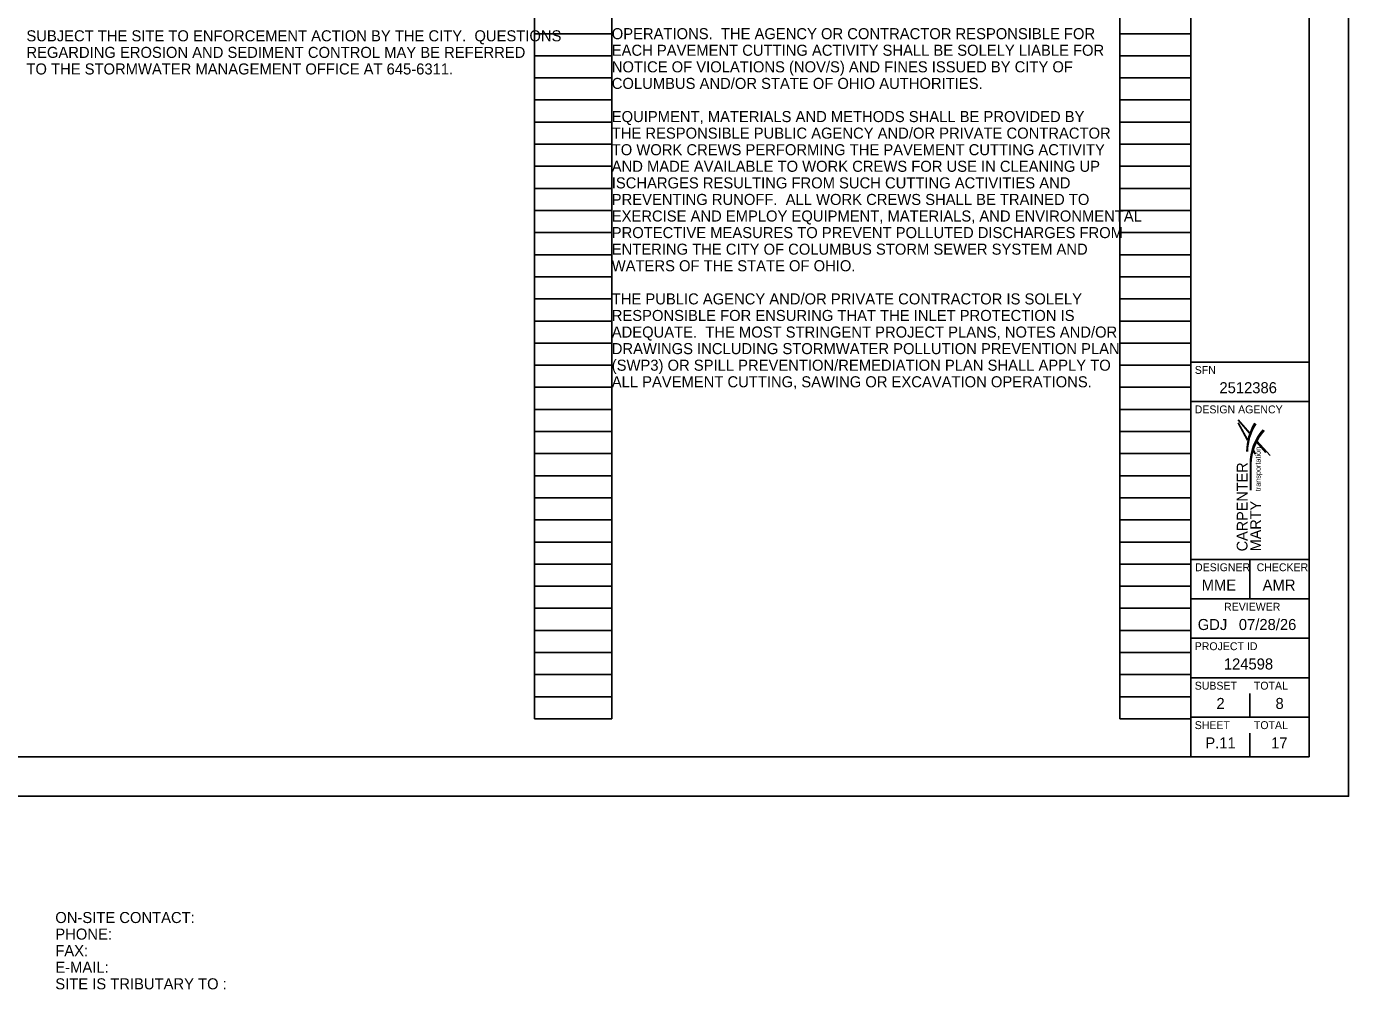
# Model space of a CAD drawing. Extents: x 0 to 34, y -2.4 to 26.3.
# Drawn here: x 17.24 to 34, y -2.45 to 9.75 of the extents above; entities that cross this region are included whole.
import ezdxf

# ---------------------------------------------------------------- set-up
doc = ezdxf.new("R2010")
doc.units = 0
for name, color, linetype in [('BR_P_Gen_Text', 7, 'Continuous'), ('SH_Border', 7, 'Continuous'), ('SH_Cut_Line', 7, 'Continuous'), ('SH_Data', 7, 'Continuous'), ('SH_Text', 7, 'Continuous')]:
    doc.layers.add(name, color=color, linetype=linetype)

msp = doc.modelspace()

# ---------------------------------------------------------------- linework, layer by layer
at = {"layer": 'SH_Border'}
for p, q in [((32, 0.5), (32, 21.5)), ((32, 5.5), (33.5, 5.5)), ((32, 5), (33.5, 5)), ((32, 3), (33.5, 3)), ((32.75, 3), (32.75, 2.5)), ((32, 2.5), (33.5, 2.5)), ((32, 2), (33.5, 2)), ((32, 1.5), (33.5, 1.5)), ((32, 1), (33.5, 1))]:
    msp.add_line(p, q, dxfattribs=at)
msp.add_lwpolyline([(1.5, 21.5), (33.5, 21.5), (33.5, 0.5), (1.5, 0.5)], close=True, dxfattribs=at)
at = {"layer": 'SH_Cut_Line'}
msp.add_lwpolyline([(0, 0), (34, 0), (34, 22), (0, 22)], close=True, dxfattribs=at)
at = {"layer": 'SH_Data'}
for p, q in [((23.68, 0.98), (23.68, 21.14)), ((24.66, 0.98), (24.66, 21.14)), ((31.1, 0.98), (31.1, 21.14)), ((32, 0.98), (32, 21.14)), ((23.68, 9.66), (24.66, 9.66)), ((31.1, 9.66), (32, 9.66)), ((23.68, 9.38), (24.66, 9.38)), ((31.1, 9.38), (32, 9.38)), ((23.68, 9.1), (24.66, 9.1)), ((31.1, 9.1), (32, 9.1)), ((23.68, 8.82), (24.66, 8.82)), ((31.1, 8.82), (32, 8.82)), ((23.68, 8.54), (24.66, 8.54)), ((31.1, 8.54), (32, 8.54)), ((23.68, 8.26), (24.66, 8.26)), ((31.1, 8.26), (32, 8.26)), ((23.68, 7.98), (24.66, 7.98)), ((31.1, 7.98), (32, 7.98)), ((23.68, 7.7), (24.66, 7.7)), ((31.1, 7.7), (32, 7.7)), ((23.68, 7.42), (24.66, 7.42)), ((31.1, 7.42), (32, 7.42)), ((23.68, 7.14), (24.66, 7.14)), ((31.1, 7.14), (32, 7.14)), ((23.68, 6.86), (24.66, 6.86)), ((31.1, 6.86), (32, 6.86)), ((23.68, 6.58), (24.66, 6.58)), ((31.1, 6.58), (32, 6.58)), ((23.68, 6.3), (24.66, 6.3)), ((31.1, 6.3), (32, 6.3)), ((23.68, 6.02), (24.66, 6.02)), ((31.1, 6.02), (32, 6.02)), ((23.68, 5.74), (24.66, 5.74)), ((31.1, 5.74), (32, 5.74)), ((23.68, 5.46), (24.66, 5.46)), ((31.1, 5.46), (32, 5.46)), ((23.68, 5.18), (24.66, 5.18)), ((31.1, 5.18), (32, 5.18)), ((23.68, 4.9), (24.66, 4.9)), ((31.1, 4.9), (32, 4.9)), ((23.68, 4.62), (24.66, 4.62)), ((31.1, 4.62), (32, 4.62)), ((23.68, 4.34), (24.66, 4.34)), ((31.1, 4.34), (32, 4.34)), ((23.68, 4.06), (24.66, 4.06)), ((31.1, 4.06), (32, 4.06)), ((32.75, 4), (32.75, 4)), ((23.68, 3.78), (24.66, 3.78)), ((31.1, 3.78), (32, 3.78)), ((23.68, 3.5), (24.66, 3.5)), ((31.1, 3.5), (32, 3.5)), ((23.68, 3.22), (24.66, 3.22)), ((31.1, 3.22), (32, 3.22)), ((23.68, 2.94), (24.66, 2.94)), ((31.1, 2.94), (32, 2.94)), ((23.68, 2.66), (24.66, 2.66)), ((31.1, 2.66), (32, 2.66)), ((23.68, 2.38), (24.66, 2.38)), ((31.1, 2.38), (32, 2.38)), ((23.68, 2.1), (24.66, 2.1)), ((31.1, 2.1), (32, 2.1)), ((23.68, 1.82), (24.66, 1.82)), ((31.1, 1.82), (32, 1.82)), ((23.68, 1.54), (24.66, 1.54)), ((31.1, 1.54), (32, 1.54)), ((23.68, 1.26), (24.66, 1.26)), ((31.1, 1.26), (32, 1.26)), ((32.75, 1), (32.75, 1.3)), ((23.68, 0.98), (24.66, 0.98)), ((31.1, 0.98), (32, 0.98)), ((32.375, 0.675), (32.375, 0.675)), ((32.75, 0.5), (32.75, 0.8))]:
    msp.add_line(p, q, dxfattribs=at)
at = {"layer": 'SH_Text'}
for p, q in [((32.721, 4.516), (32.602, 4.732)), ((32.811, 4.34), (32.79, 4.38)), ((32.82, 4.334), (32.791, 4.386)), ((32.952, 4.353), (32.834, 4.491)), ((32.839, 4.502), (33.006, 4.316)), ((32.755, 3.878), (32.755, 4.204)), ((32.762, 3.878), (32.762, 4.204))]:
    msp.add_line(p, q, dxfattribs=at)
for points in [[(32.746, 4.604), (32.601, 4.766)], [(32.601, 4.766), (32.744, 4.598)], [(32.721, 4.516), (32.602, 4.732)], [(32.602, 4.732), (32.719, 4.511)]]:
    msp.add_lwpolyline(points, dxfattribs=at)
for centre, radius, start, end in [((33.432, 4.36), 0.721, 149.5704, 179.5529), ((33.373, 4.362), 0.654, 147.1423, 179.6525), ((33.426, 4.204), 0.671, 139.2898, 180.0106), ((33.433, 4.188), 0.672, 138.5126, 178.6075)]:
    msp.add_arc(centre, radius, start, end, dxfattribs=at)

# ---------------------------------------------------------------- texts
at = {"layer": 'BR_P_Gen_Text'}
for s, p in [('OPERATIONS.  THE AGENCY OR CONTRACTOR RESPONSIBLE FOR ', (24.66, 9.59)), ('SUBJECT THE SITE TO ENFORCEMENT ACTION BY THE CITY.  QUESTIONS ', (17.24, 9.563)), ('REGARDING EROSION AND SEDIMENT CONTROL MAY BE REFERRED ', (17.24, 9.353)), ('EACH PAVEMENT CUTTING ACTIVITY SHALL BE SOLELY LIABLE FOR ', (24.66, 9.38)), ('TO THE STORMWATER MANAGEMENT OFFICE AT 645-6311.', (17.24, 9.143)), ('NOTICE OF VIOLATIONS (NOV/S) AND FINES ISSUED BY CITY OF ', (24.66, 9.17)), ('COLUMBUS AND/OR STATE OF OHIO AUTHORITIES.', (24.66, 8.96)), ('EQUIPMENT, MATERIALS AND METHODS SHALL BE PROVIDED BY ', (24.66, 8.54)), ('THE RESPONSIBLE PUBLIC AGENCY AND/OR PRIVATE CONTRACTOR ', (24.66, 8.33)), ('TO WORK CREWS PERFORMING THE PAVEMENT CUTTING ACTIVITY ', (24.66, 8.12)), ('AND MADE AVAILABLE TO WORK CREWS FOR USE IN CLEANING UP ', (24.66, 7.91)), ('ISCHARGES RESULTING FROM SUCH CUTTING ACTIVITIES AND ', (24.66, 7.7)), ('PREVENTING RUNOFF.  ALL WORK CREWS SHALL BE TRAINED TO ', (24.66, 7.49)), ('EXERCISE AND EMPLOY EQUIPMENT, MATERIALS, AND ENVIRONMENTAL ', (24.66, 7.28)), ('PROTECTIVE MEASURES TO PREVENT POLLUTED DISCHARGES FROM ', (24.66, 7.07)), ('ENTERING THE CITY OF COLUMBUS STORM SEWER SYSTEM AND ', (24.66, 6.86)), ('WATERS OF THE STATE OF OHIO.', (24.66, 6.65)), ('THE PUBLIC AGENCY AND/OR PRIVATE CONTRACTOR IS SOLELY ', (24.66, 6.23)), ('RESPONSIBLE FOR ENSURING THAT THE INLET PROTECTION IS ', (24.66, 6.02)), ('ADEQUATE.  THE MOST STRINGENT PROJECT PLANS, NOTES AND/OR ', (24.66, 5.81)), ('DRAWINGS INCLUDING STORMWATER POLLUTION PREVENTION PLAN ', (24.66, 5.6)), ('(SWP3) OR SPILL PREVENTION/REMEDIATION PLAN SHALL APPLY TO ', (24.66, 5.39)), ('ALL PAVEMENT CUTTING, SAWING OR EXCAVATION OPERATIONS.', (24.66, 5.18))]:
    msp.add_text(s, height=0.14, dxfattribs=at).set_placement(p)
at = {"layer": 'SH_Data'}
for s, height, p in [('SFN', 0.1, (32.05, 5.35)), ('2512386', 0.14, (32.363, 5.105)), ('DESIGN AGENCY', 0.1, (32.05, 4.85)), ('DESIGNER', 0.1, (32.054, 2.85)), ('CHECKER', 0.1, (32.835, 2.85)), ('MME', 0.14, (32.138, 2.605)), ('AMR', 0.14, (32.911, 2.605)), ('REVIEWER', 0.1, (32.422, 2.35)), ('GDJ', 0.14, (32.088, 2.105)), ('07/28/26', 0.14, (32.609, 2.105)), ('PROJECT ID', 0.1, (32.05, 1.85)), ('124598', 0.14, (32.419, 1.605)), ('SUBSET', 0.1, (32.05, 1.35)), ('TOTAL', 0.1, (32.8, 1.35)), ('2', 0.14, (32.325, 1.105)), ('8', 0.14, (33.074, 1.105)), ('SHEET', 0.1, (32.05, 0.85)), ('TOTAL', 0.1, (32.8, 0.85)), ('P.11', 0.14, (32.184, 0.605)), ('17', 0.14, (33.018, 0.605))]:
    msp.add_text(s, height=height, dxfattribs=at).set_placement(p)
at = {"layer": 'SH_Text'}
for s, height, p in [('transportation', 0.06649, (32.885, 3.864)), ('CARPENTER ', 0.1367, (32.719, 3.102)), ('MARTY', 0.1367, (32.891, 3.102))]:
    msp.add_text(s, height=height, rotation=90, dxfattribs=at).set_placement(p)
for s, p in [('ON-SITE CONTACT:', (17.606, -1.607)), ('PHONE:', (17.606, -1.817)), ('FAX:', (17.606, -2.027)), ('E-MAIL:', (17.606, -2.237)), ('SITE IS TRIBUTARY TO :', (17.606, -2.447))]:
    msp.add_text(s, height=0.14, dxfattribs=at).set_placement(p)

doc.saveas('drawing.dxf')
